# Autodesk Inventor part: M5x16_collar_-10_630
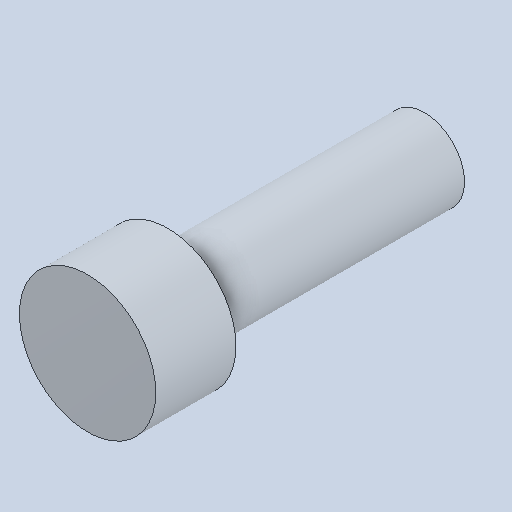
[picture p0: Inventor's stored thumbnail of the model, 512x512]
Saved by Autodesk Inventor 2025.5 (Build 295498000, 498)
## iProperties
Created: 2026-10
Part Number: M5x16_collar_-10_630
Material: Genérico
Document SubType Name: Modeling
Designer: Luis M
Density: 1 g/cm^3
Appearance: Valor por defecto
Author: Luis M
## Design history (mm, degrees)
feature "Base1"
node "Sólido1"
